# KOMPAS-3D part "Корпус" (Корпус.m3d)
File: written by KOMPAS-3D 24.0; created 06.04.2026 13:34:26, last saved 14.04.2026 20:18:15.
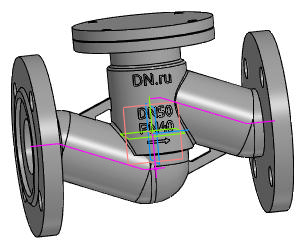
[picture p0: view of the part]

Document properties: Автор: R2D2; Полное имя файла: E:\Работа\Зайцев\VSO3131M-F-S Клапан запорный DN.ru Ду15-100 Ру40\DN50\исходные материалы\Корпус.m3d

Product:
- Body: Труба / Нестандартная труба / L = 116.1 мм  | qty 1
    Материал: Нестандартная труба (density 7856 kg/m3)
    Масса: 13.252607
    Раздел спецификации: Детали
    Примечание: 2,58 кг
    additional columns: Pipeline; 0.06; 0; 0; 0.002; 0.11611; true; 0.04
- Body: Труба / Нестандартная труба / L = 145.1 мм  | qty 1
    Материал: Нестандартная труба (density 7856 kg/m3)
    Масса: 13.252607
    Раздел спецификации: Детали
    Примечание: 3,22 кг
    additional columns: Pipeline; 0.06; 0; 0; 0.002; 0.14505; true; 0.04
- Body: Тело 4  | qty 1
    Материал: Нестандартная труба (density 7856 kg/m3)
    Масса: 13.252607
- Body: Тело 5  | qty 1
    Материал: Нестандартная труба (density 7856 kg/m3)
    Масса: 13.252607
- Body: Тело 8  | qty 1
    Материал: Нестандартная труба (density 7856 kg/m3)
    Масса: 13.252607
- Body: Тело 9  | qty 1
    Материал: Нестандартная труба (density 7856 kg/m3)
    Масса: 13.252607
- Part/product: Корпус
    Масса: 6.9

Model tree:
1. Труба
2. Труба:1  (labels: {F703FF30-5BE6-4673-A7F1-8EDA1BE1E2D1}; SHAPEOBJECT3D_ATTR_BUTT; SHAPEOBJECT3D_ATTR_VALID; SHAPEOBJECT3D_ATTR_BUTT_AREA)
     PIPE_R = 7
3. Труба:2  (labels: {F703FF30-5BE6-4673-A7F1-8EDA1BE1E2D1}; SHAPEOBJECT3D_ATTR_BUTT; SHAPEOBJECT3D_ATTR_VALID; SHAPEOBJECT3D_ATTR_BUTT_AREA)
     PIPE_R = 5
4. Колонна
5. Элемент выдавливания:1
     Смещение 1 = -1; Смещение 2 = -5
6. Скругление:17  (with: Ребро.Элемент выдавливания:1)
     Радиус = 1
7. Скругление:18  (with: Ребро.Элемент выдавливания:1)
8. Скругление:24  (with: Ребро.Элемент выдавливания:1)
     Радиус = 0.5
9. Элемент выдавливания:2
     Расстояние 1 = 6
10. Скругление:19  (with: Ребро.Элемент выдавливания:2)
     Радиус = 2
11. Эскиз:4  (with: Грань.Элемент выдавливания:1)
12. Элемент выдавливания:3
     Расстояние 1 = 17.5
13. Скругление:21  (with: Ребро.Элемент выдавливания:3)
14. ОТЛИВКА
15. Скругление:6  (with: Грань.Элемент выдавливания:1)
     Радиус = 2
16. Элемент выдавливания:6  (with: Грань.Элемент выдавливания:1)
     Смещение 1 = 4
17. ЛЕЙБЛ
18. Элемент выдавливания:7  (with: Грань.Элемент выдавливания:1)
     Расстояние 1 = 35.9997; Смещение 1 = 1
19. Фланец верх  (with: Ребро.Элемент выдавливания:3)
20. Элемент вращения:2
     Угол 1 = 360
21. Эскиз:12  (with: Грань.Элемент вращения:2)
22. Элемент выдавливания:9  (with: Грань.Элемент вращения:2)
     Расстояние 2 = 20
23. Массив по концентрической сетке:1  (with: Элемент выдавливания:9, Эскиз:12, Грань.Элемент вращения:2)  (4 pattern instances)
     Шаг 2 = 360
24. Фланец
25. Элемент вращения:1
     Угол 1 = 360
26. отвертие во фланце  (with: Грань.Элемент вращения:1)
27. Элемент выдавливания:8
28. Массив по концентрической сетке:2  (with: Элемент выдавливания:8, Эскиз:10, Грань.Элемент вращения:1)  (4 pattern instances)
     Шаг 2 = 360
29. Зеркальный массив:1
30. Экземпляр ( 1 )
31. Экземпляр ( 2 )  (with: Элемент вращения:1, Массив по концентрической сетке:2, Экземпляр ( 1 ), Элемент выдавливания:8)
32. Экземпляр ( 3 )  (with: Элемент выдавливания:8)
33. Экземпляр ( 4 )  (with: Элемент выдавливания:8)
34. Скругление:25  (with: Ребро.Элемент вращения:2)
     Радиус = 2
35. Скругление:26
     Радиус = 2

Expressions: DS/2+3; D1/2; DN/2; D/2; DS-v977*4; LL/2; D1-v1234*2
Referenced files in C:\Program Files\ASCON\KOMPAS-3D v24\Libs\Pipeline\: StylesTemplate.a3d, TemplateHPH, InsulationStylesTemplate.a3d, Insulation
Referenced files in C:\Program Files\ASCON\KOMPAS-3D v24\Templates\: Констр. чертеж А3 гориз. перв. лист.cdt
Referenced files in E:\Работа\Зайцев\VSO3131M-F-S Клапан запорный DN.ru Ду15-100 Ру40\DN20\исходные материалы\: 
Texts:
  Отводы ГОСТ 17375-2001
  Констр. чертеж А3 гориз. перв. лист.cdt
  GOST 26.020 Pr3
  var3D
  смещение колонны вниз
  LL-10
  DN+10
  Труба / Нестандартная труба / L = %s мм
